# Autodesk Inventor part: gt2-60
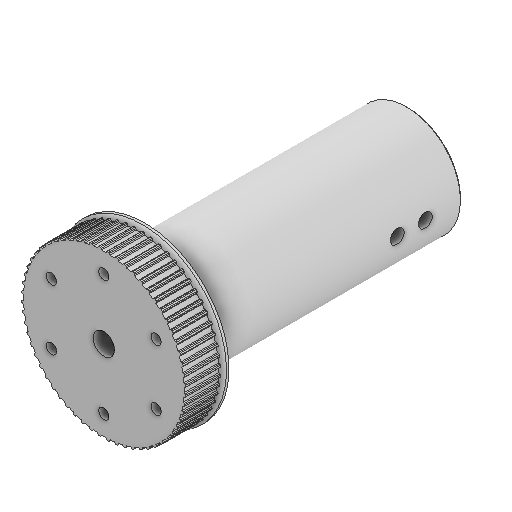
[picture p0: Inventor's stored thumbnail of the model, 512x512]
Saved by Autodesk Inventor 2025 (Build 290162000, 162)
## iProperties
Created: 2025-06
Part Number: gt2-60
Material: Generico
Document SubType Name: Modeling
Designer: Ryzen5700u
Density: 1 g/cm^3
Appearance: Default
Author: Ryzen5700u
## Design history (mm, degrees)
sketch "Schizzo1"
  geometry: C1 r 4.963 at (0, 0); A1 r 18.592 centre (0, 0) between (-0.5, -18.585) and (0.5, -18.585); A2 r 0.65 centre (0, -19) between (0.628, -18.833) and (0.5, -18.585); A3 r 0.2 centre (0.822, -18.782) between (0.628, -18.833) and (0.83, -18.982); A4 r 19 centre (0, 0) between (0.83, -18.982) and (1.158, -18.965); A5 r 0.2 centre (1.146, -18.765) between (1.158, -18.965) and (1.344, -18.796); A6 r 0.65 centre (1.986, -18.896) between (1.445, -18.536) and (1.344, -18.796); A7 r 18.592 centre (0, 0) between (1.445, -18.536) and (2.44, -18.431); A8 r 0.65 centre (1.986, -18.896) between (2.593, -18.664) and (2.44, -18.431); A9 r 0.2 centre (2.78, -18.593) between (2.593, -18.664) and (2.81, -18.791); A10 r 19 centre (0, 0) between (2.81, -18.791) and (3.134, -18.74); A11 r 0.2 centre (3.101, -18.542) between (3.134, -18.74) and (3.301, -18.552); A12 r 0.65 centre (3.95, -18.585) between (3.375, -18.283) and (3.301, -18.552); A13 r 18.592 centre (0, 0) between (3.375, -18.283) and (4.354, -18.075); A14 r 0.65 centre (3.95, -18.585) between (4.53, -18.291) and (4.354, -18.075); A15 r 0.2 centre (4.709, -18.201) between (4.53, -18.291) and (4.759, -18.394); A16 r 19 centre (0, 0) between (4.759, -18.394) and (5.076, -18.309); A17 r 0.2 centre (5.023, -18.117) between (5.076, -18.309) and (5.222, -18.106); A18 r 0.65 centre (5.871, -18.07) between (5.267, -17.83) and (5.222, -18.106); A19 r 18.592 centre (0, 0) between (5.267, -17.83) and (6.219, -17.521); A20 r 0.65 centre (5.871, -18.07) between (6.417, -17.717) and (6.219, -17.521); A21 r 0.2 centre (6.585, -17.609) between (6.417, -17.717) and (6.655, -17.796); A22 r 19 centre (0, 0) between (6.655, -17.796) and (6.962, -17.679); A23 r 0.2 centre (6.889, -17.492) between (6.962, -17.679) and (7.086, -17.461); A24 r 0.65 centre (7.728, -17.357) between (7.102, -17.182) and (7.086, -17.461); A25 r 18.592 centre (0, 0) between (7.102, -17.182) and (8.017, -16.775); A26 r 0.65 centre (7.728, -17.357) between (8.234, -16.95) and (8.017, -16.775); A27 r 0.2 centre (8.39, -16.824) between (8.234, -16.95) and (8.479, -17.003); A28 r 19 centre (0, 0) between (8.479, -17.003) and (8.772, -16.854); A29 r 0.2 centre (8.68, -16.677) between (8.772, -16.854) and (8.873, -16.624); A30 r 0.65 centre (9.5, -16.454) between (8.859, -16.346) and (8.873, -16.624); A31 r 18.592 centre (0, 0) between (8.859, -16.346) and (9.726, -15.845); A32 r 0.65 centre (9.5, -16.454) between (9.961, -15.996) and (9.726, -15.845); A33 r 0.2 centre (10.103, -15.855) between (9.961, -15.996) and (10.21, -16.024); A34 r 19 centre (0, 0) between (10.21, -16.024) and (10.486, -15.845); A35 r 0.2 centre (10.375, -15.678) between (10.486, -15.845) and (10.562, -15.606); A36 r 0.65 centre (11.168, -15.371) between (10.519, -15.33) and (10.562, -15.606); A37 r 18.592 centre (0, 0) between (10.519, -15.33) and (11.329, -14.742); A38 r 0.65 centre (11.168, -15.371) between (11.578, -14.867) and (11.329, -14.742); A39 r 0.2 centre (11.704, -14.712) between (11.578, -14.867) and (11.829, -14.869); A40 r 19 centre (0, 0) between (11.829, -14.869) and (12.084, -14.662); A41 r 0.2 centre (11.957, -14.508) between (12.084, -14.662) and (12.135, -14.416); A42 r 0.65 centre (12.713, -14.12) between (12.064, -14.146) and (12.135, -14.416); A43 r 18.592 centre (0, 0) between (12.064, -14.146) and (12.808, -13.477); A44 r 0.65 centre (12.713, -14.12) between (13.069, -13.575) and (12.808, -13.477); A45 r 0.2 centre (13.178, -13.408) between (13.069, -13.575) and (13.318, -13.551); A46 r 19 centre (0, 0) between (13.318, -13.551) and (13.551, -13.318); A47 r 0.2 centre (13.408, -13.178) between (13.551, -13.318) and (13.575, -13.069); A48 r 0.65 centre (14.12, -12.713) between (13.477, -12.808) and (13.575, -13.069); A49 r 18.592 centre (0, 0) between (13.477, -12.808) and (14.146, -12.064); A50 r 0.65 centre (14.12, -12.713) between (14.416, -12.135) and (14.146, -12.064); A51 r 0.2 centre (14.508, -11.957) between (14.416, -12.135) and (14.662, -12.084); A52 r 19 centre (0, 0) between (14.662, -12.084) and (14.869, -11.829); A53 r 0.2 centre (14.712, -11.704) between (14.869, -11.829) and (14.867, -11.578); A54 r 0.65 centre (15.371, -11.168) between (14.742, -11.329) and (14.867, -11.578); A55 r 18.592 centre (0, 0) between (14.742, -11.329) and (15.33, -10.519); A56 r 0.65 centre (15.371, -11.168) between (15.606, -10.562) and (15.33, -10.519); A57 r 0.2 centre (15.678, -10.375) between (15.606, -10.562) and (15.845, -10.486); A58 r 19 centre (0, 0) between (15.845, -10.486) and (16.024, -10.21); A59 r 0.2 centre (15.855, -10.103) between (16.024, -10.21) and (15.996, -9.961); A60 r 0.65 centre (16.454, -9.5) between (15.845, -9.726) and (15.996, -9.961); A61 r 18.592 centre (0, 0) between (15.845, -9.726) and (16.346, -8.859); A62 r 0.65 centre (16.454, -9.5) between (16.624, -8.873) and (16.346, -8.859); A63 r 0.2 centre (16.677, -8.68) between (16.624, -8.873) and (16.854, -8.772); A64 r 19 centre (0, 0) between (16.854, -8.772) and (17.003, -8.479)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; 361 further points
  constraints: 720 point on circle, 361 centre point
extrude "Estrusione1" new body sketch "Schizzo1" stored distance "d0" = 7; taper "d1" = 0 deg
sketch "Schizzo2"
  geometry: C1 r 19.5 at (0, 0); 1 further point
  constraints: 1 centre point, 1 coincident
  dimensions: "d2" = 39 diameter of C1
extrude "Estrusione2" join sketch "Schizzo2" distance "d3" = 1.5; taper "d4" = 0 deg
sketch "Schizzo3"
  geometry: C1 r 12.5 at (0, 0); 1 further point
  constraints: 1 centre point, 1 coincident
  dimensions: "d5" = 25 diameter of C1
extrude "Estrusione3" join sketch "Schizzo3" distance "d6" = 61; taper "d7" = 0 deg
sketch "Schizzo4"
  geometry: C1 r 12.5 at (0, 0) reference; C2 r 10 at (0, 0); C3 r 14 at (0, 0); 1 further point
  constraints: 2 centre point, 1 coincident
  dimensions: "d23" = 1.5 radial gap between concentric circles of C1 C3
extrude "Estrusione4" join sketch "Schizzo4" distance "d9" = 2; taper "d10" = 0 deg
chamfer "Smusso1" distance "d11" = 0.4; stored, may be unused: second distance "d12" = 2, angle "d13" = 45 deg
sketch "Schizzo5"
  geometry: 1 further point
hole "Foro1" sketch "Schizzo5" at (0, 0) diameter "d14" = 5.5; stored, may be unused: countersink angle "d18" = 90 deg, drill point angle "d20" = 0 deg; dims "d15" = 6, "d16" = 10, "d17" = 5.7, "d19" = 50
sketch "Schizzo6"
  geometry: L1 (12.1, -66)-(-12.1, -66) reference; C1 r 1.6 at (0, -51); C2 r 1.7 at (0, -52) reference; C3 r 1.6 at (0, -57.5); 1 further point
  constraints: 2 centre point
  dimensions: "d37" = 15 distance from line of L1 C1.centre; "d38" = 3.2 diameter of C1; "d39" = 3.2 diameter of C3; "d40" = 6.5 distance of C3.centre C1.centre
extrude "Estrusione5" cut sketch "Schizzo6" extent not by distance; stored distance "d21" = 0; taper "d22" = 0 deg
fillet "Raccordo1" dims "d24" = 1.5
sketch "Schizzo7"
  geometry: C1 r 12.5 at (0, 0) reference; A1 r 19 centre (0, 0) between (-1.158, -18.965) and (-0.83, -18.982) reference; A2 r 0.2 centre (-0.822, -18.782) between (-0.83, -18.982) and (-0.628, -18.833) reference; A3 r 0.65 centre (0, -19) between (-0.5, -18.585) and (-0.628, -18.833) reference; A4 r 18.592 centre (0, 0) between (-0.5, -18.585) and (0.5, -18.585) reference; A5 r 0.65 centre (0, -19) between (0.628, -18.833) and (0.5, -18.585) reference; A6 r 0.2 centre (0.822, -18.782) between (0.628, -18.833) and (0.83, -18.982) reference; A7 r 19 centre (0, 0) between (0.83, -18.982) and (1.158, -18.965) reference; A8 r 0.2 centre (1.146, -18.765) between (1.158, -18.965) and (1.344, -18.796) reference; A9 r 0.65 centre (1.986, -18.896) between (1.445, -18.536) and (1.344, -18.796) reference; A10 r 18.592 centre (0, 0) between (1.445, -18.536) and (2.44, -18.431) reference; A11 r 0.65 centre (1.986, -18.896) between (2.593, -18.664) and (2.44, -18.431) reference; A12 r 0.2 centre (2.78, -18.593) between (2.593, -18.664) and (2.81, -18.791) reference; A13 r 19 centre (0, 0) between (2.81, -18.791) and (3.134, -18.74) reference; A14 r 0.2 centre (3.101, -18.542) between (3.134, -18.74) and (3.301, -18.552) reference; A15 r 0.65 centre (3.95, -18.585) between (3.375, -18.283) and (3.301, -18.552) reference; A16 r 18.592 centre (0, 0) between (3.375, -18.283) and (4.354, -18.075) reference; A17 r 0.65 centre (3.95, -18.585) between (4.53, -18.291) and (4.354, -18.075) reference; A18 r 0.2 centre (4.709, -18.201) between (4.53, -18.291) and (4.759, -18.394) reference; A19 r 19 centre (0, 0) between (4.759, -18.394) and (5.076, -18.309) reference; A20 r 0.2 centre (5.023, -18.117) between (5.076, -18.309) and (5.222, -18.106) reference; A21 r 0.65 centre (5.871, -18.07) between (5.267, -17.83) and (5.222, -18.106) reference; A22 r 18.592 centre (0, 0) between (5.267, -17.83) and (6.219, -17.521) reference; A23 r 0.65 centre (5.871, -18.07) between (6.417, -17.717) and (6.219, -17.521) reference; A24 r 0.2 centre (6.585, -17.609) between (6.417, -17.717) and (6.655, -17.796) reference; A25 r 19 centre (0, 0) between (6.655, -17.796) and (6.962, -17.679) reference; A26 r 0.2 centre (6.889, -17.492) between (6.962, -17.679) and (7.086, -17.461) reference; A27 r 0.65 centre (7.728, -17.357) between (7.102, -17.182) and (7.086, -17.461) reference; A28 r 18.592 centre (0, 0) between (7.102, -17.182) and (8.017, -16.775) reference; A29 r 0.65 centre (7.728, -17.357) between (8.234, -16.95) and (8.017, -16.775) reference; A30 r 0.2 centre (8.39, -16.824) between (8.234, -16.95) and (8.479, -17.003) reference; A31 r 19 centre (0, 0) between (8.479, -17.003) and (8.772, -16.854) reference; A32 r 0.2 centre (8.68, -16.677) between (8.772, -16.854) and (8.873, -16.624) reference; A33 r 0.65 centre (9.5, -16.454) between (8.859, -16.346) and (8.873, -16.624) reference; A34 r 18.592 centre (0, 0) between (8.859, -16.346) and (9.726, -15.845) reference; A35 r 0.65 centre (9.5, -16.454) between (9.961, -15.996) and (9.726, -15.845) reference; A36 r 0.2 centre (10.103, -15.855) between (9.961, -15.996) and (10.21, -16.024) reference; A37 r 19 centre (0, 0) between (10.21, -16.024) and (10.486, -15.845) reference; A38 r 0.2 centre (10.375, -15.678) between (10.486, -15.845) and (10.562, -15.606) reference; A39 r 0.65 centre (11.168, -15.371) between (10.519, -15.33) and (10.562, -15.606) reference; A40 r 18.592 centre (0, 0) between (10.519, -15.33) and (11.329, -14.742) reference; A41 r 0.65 centre (11.168, -15.371) between (11.578, -14.867) and (11.329, -14.742) reference; A42 r 0.2 centre (11.704, -14.712) between (11.578, -14.867) and (11.829, -14.869) reference; A43 r 19 centre (0, 0) between (11.829, -14.869) and (12.084, -14.662) reference; A44 r 0.2 centre (11.957, -14.508) between (12.084, -14.662) and (12.135, -14.416) reference; A45 r 0.65 centre (12.713, -14.12) between (12.064, -14.146) and (12.135, -14.416) reference; A46 r 18.592 centre (0, 0) between (12.064, -14.146) and (12.808, -13.477) reference; A47 r 0.65 centre (12.713, -14.12) between (13.069, -13.575) and (12.808, -13.477) reference; A48 r 0.2 centre (13.178, -13.408) between (13.069, -13.575) and (13.318, -13.551) reference; A49 r 19 centre (0, 0) between (13.318, -13.551) and (13.551, -13.318) reference; A50 r 0.2 centre (13.408, -13.178) between (13.551, -13.318) and (13.575, -13.069) reference; A51 r 0.65 centre (14.12, -12.713) between (13.477, -12.808) and (13.575, -13.069) reference; A52 r 18.592 centre (0, 0) between (13.477, -12.808) and (14.146, -12.064) reference; A53 r 0.65 centre (14.12, -12.713) between (14.416, -12.135) and (14.146, -12.064) reference; A54 r 0.2 centre (14.508, -11.957) between (14.416, -12.135) and (14.662, -12.084) reference; A55 r 19 centre (0, 0) between (14.662, -12.084) and (14.869, -11.829) reference; A56 r 0.2 centre (14.712, -11.704) between (14.869, -11.829) and (14.867, -11.578) reference; A57 r 0.65 centre (15.371, -11.168) between (14.742, -11.329) and (14.867, -11.578) reference; A58 r 18.592 centre (0, 0) between (14.742, -11.329) and (15.33, -10.519) reference; A59 r 0.65 centre (15.371, -11.168) between (15.606, -10.562) and (15.33, -10.519) reference; A60 r 0.2 centre (15.678, -10.375) between (15.606, -10.562) and (15.845, -10.486) reference; A61 r 19 centre (0, 0) between (15.845, -10.486) and (16.024, -10.21) reference; A62 r 0.2 centre (15.855, -10.103) between (16.024, -10.21) and (15.996, -9.961) reference; A63 r 0.65 centre (16.454, -9.5) between (15.845, -9.726) and (15.996, -9.961) reference; A64 r 18.592 centre (0, 0) between (15.845, -9.726) and (16.346, -8.859) reference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; 1 further point
extrude "Estrusione6" join sketch "Schizzo7" distance "d25" = 1; taper "d26" = 0 deg
sketch "Schizzo8"
  geometry: 4 further points
  constraints: 1 coincident, 1 vertical alignment, 1 other
hole "Foro2" sketch "Schizzo8" at (0, 14) diameter "d27" = 2.4; stored, may be unused: countersink angle "d31" = 90 deg, drill point angle "d33" = 118 deg; dims "d28" = 6, "d29" = 4.4, "d30" = 2.3, "d32" = 7
pattern_circular "Serie circolare1" dims angle "d35" = 360 deg
sketch "Schizzo9"
  geometry: 2 further points
hole "Foro3" sketch "Schizzo9" at (0, 0) diameter "d41" = 5; stored, may be unused: countersink angle "d45" = 90 deg, drill point angle "d47" = 118 deg; dims "d42" = 6, "d43" = 5.5, "d44" = 2, "d46" = 8
fillet "Raccordo2" dims "d48" = 0.9
node "Solido1"
node "Riferimento2"
node "Riferimento3"
node "Linea chiusa proiettata1"
